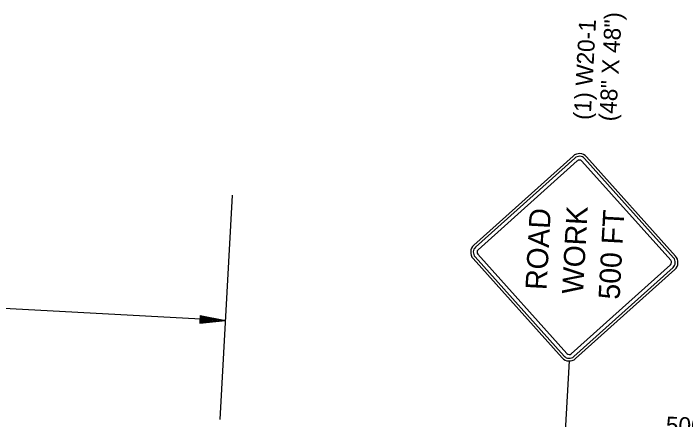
# Model space of a CAD drawing. Extents: x 879461 to 881100, y 1566470 to 1567598.
# Drawn here: x 880385 to 880623.3, y 1567239 to 1567382.9 of the extents above; entities that cross this region are included whole.
import ezdxf

# ---------------------------------------------------------------- set-up
doc = ezdxf.new("R2010")
doc.units = 0
for name, color, linetype in [('P_TC_Signs_Temporary', 7, 'Continuous'), ('R_Annotation', 7, 'Continuous'), ('R_Draft', 7, 'Continuous')]:
    doc.layers.add(name, color=color, linetype=linetype)

msp = doc.modelspace()

# ---------------------------------------------------------------- linework, layer by layer
at = {"layer": 'P_TC_Signs_Temporary'}
for p, q in [((880548.21, 1567300.82), (880583.39, 1567332.37)), ((880548.84, 1567300.12), (880584.01, 1567331.67)), ((880587.45, 1567331.48), (880619, 1567296.31)), ((880588.15, 1567332.11), (880619.7, 1567296.93)), ((880549.71, 1567299.15), (880584.89, 1567330.69)), ((880586.48, 1567330.61), (880618.02, 1567295.43)), ((880579.5, 1567260.88), (880547.95, 1567296.06)), ((880580.2, 1567261.51), (880548.65, 1567296.68)), ((880581.17, 1567262.38), (880549.63, 1567297.56)), ((880617.94, 1567293.84), (880582.76, 1567262.3)), ((880618.81, 1567292.87), (880583.64, 1567261.32)), ((880619.44, 1567292.17), (880584.26, 1567260.62))]:
    msp.add_line(p, q, dxfattribs=at)
for centre, radius, start, end in [((880585.64, 1567329.86), 3.38, 41.8871, 131.8871), ((880585.64, 1567329.86), 2.44, 41.8871, 131.8871), ((880585.64, 1567329.86), 1.12, 41.8871, 131.8871), ((880550.46, 1567298.31), 3.38, 131.8871, 221.8871), ((880550.46, 1567298.31), 2.44, 131.8871, 221.8871), ((880550.46, 1567298.31), 1.13, 131.8871, 221.8871), ((880617.19, 1567294.68), 1.13, 311.8871, 41.8871), ((880617.19, 1567294.68), 2.44, 311.8871, 41.8871), ((880617.19, 1567294.68), 3.38, 311.8871, 41.8871), ((880582.01, 1567263.13), 1.12, 221.8871, 311.8871), ((880582.01, 1567263.13), 3.38, 221.8871, 311.8871), ((880582.01, 1567263.13), 2.44, 221.8871, 311.8871)]:
    msp.add_arc(centre, radius, start, end, dxfattribs=at)
at = {"layer": 'R_Draft'}
for p, q in [((880458.28, 1567239.04), (880462.6, 1567318.47)), ((880460.18, 1567274.06), (880152.51, 1567290.79)), ((880451.2, 1567275.91), (880451.05, 1567273.19)), ((880451.05, 1567273.19), (880460.18, 1567274.06)), ((880451.07, 1567273.42), (880458.67, 1567274.14)), ((880451.08, 1567273.65), (880457.11, 1567274.22)), ((880451.09, 1567273.87), (880455.61, 1567274.31)), ((880451.1, 1567274.11), (880454.07, 1567274.39)), ((880451.12, 1567274.34), (880452.56, 1567274.47)), ((880451.14, 1567274.76), (880452.56, 1567274.47)), ((880451.15, 1567274.99), (880454.07, 1567274.39)), ((880451.17, 1567275.22), (880455.61, 1567274.31)), ((880451.18, 1567275.45), (880457.11, 1567274.22)), ((880451.19, 1567275.68), (880458.67, 1567274.14)), ((880451.2, 1567275.91), (880460.18, 1567274.06)), ((880581.95, 1567259.76), (880580.59, 1567234.79))]:
    msp.add_line(p, q, dxfattribs=at)

# ---------------------------------------------------------------- texts
at = {"layer": 'P_TC_Signs_Temporary'}
for s, p in [('WORK', (880586.92, 1567283.32)), (' ROAD ', (880573.81, 1567282)), ('500 FT ', (880599.86, 1567281.39))]:
    msp.add_text(s, height=7.5, rotation=86.8871, dxfattribs=at).set_placement(p)
at = {"layer": 'R_Annotation'}
for s, p in [('(48" X 48")', (880598.58, 1567344.6)), ('(1) W20-1', (880589.59, 1567345.09))]:
    msp.add_text(s, height=6, rotation=86.8871, dxfattribs=at).set_placement(p)
at = {"layer": 'R_Draft'}
msp.add_text("500'", height=6, rotation=358.1175, dxfattribs=at).set_placement((880616.19, 1567234.05))

doc.saveas('drawing.dxf')
